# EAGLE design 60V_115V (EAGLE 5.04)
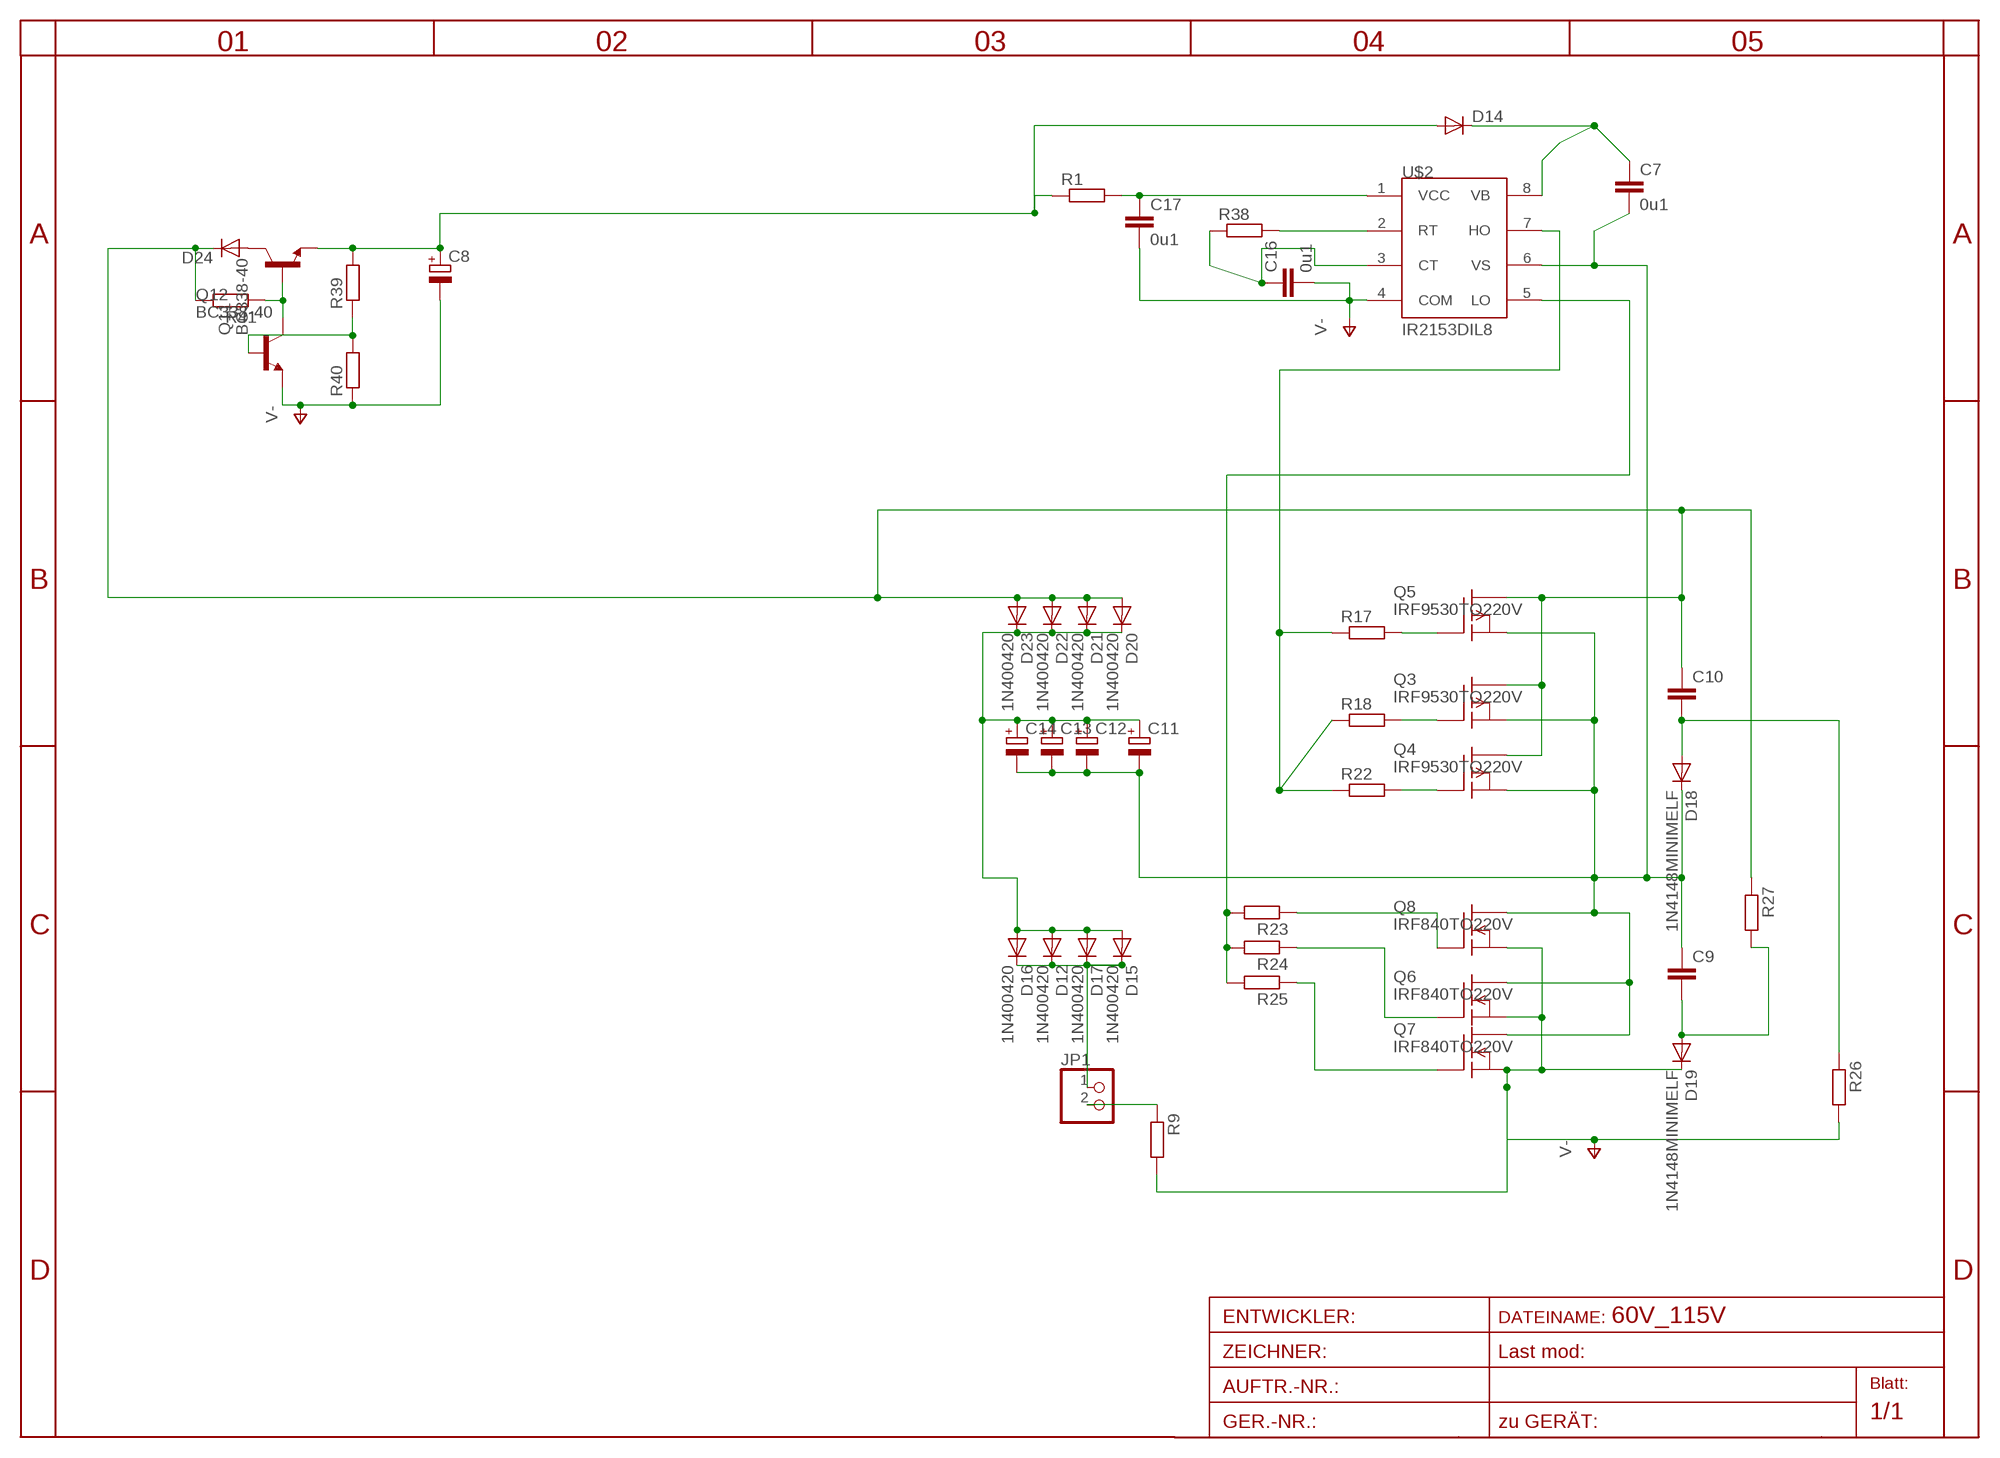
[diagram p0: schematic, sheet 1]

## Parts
C7  0u1  C-EU050-025X075  [C050-025X075]
C8  CPOL-EU5-13  [2,5-5-FLAT]
C9  C-EUC1812  [C1812]
C10  C-EUC1812K  [C1812K]
C11  CPOL-EUSANYO_SMD_E7  [SANYO-OSCON_SMD_E7]
C12  CPOL-EUSANYO_SMD_E7  [SANYO-OSCON_SMD_E7]
C13  CPOL-EUSANYO_SMD_E7  [SANYO-OSCON_SMD_E7]
C14  CPOL-EUSANYO_SMD_E7  [SANYO-OSCON_SMD_E7]
C16  0u1  C-EU025-050X050  [C025-050X050]
C17  0u1  C-EU050-030X075  [C050-030X075]
D12  1N400420  [DO41-20]
D14  DIODE-D-5  [D-5]
D15  1N400420  [DO41-20]
D16  1N400420  [DO41-20]
D17  1N400420  [DO41-20]
D18  1N4148MINIMELF  [MINIMELF]
D19  1N4148MINIMELF  [MINIMELF]
D20  1N400420  [DO41-20]
D21  1N400420  [DO41-20]
D22  1N400420  [DO41-20]
D23  1N400420  [DO41-20]
D24  DIODE-D-7.5  [D-7.5]
JP1  PINHD-1X2  [1X02]
Q3  IRF9530TO220V  [TO220V]
Q4  IRF9530TO220V  [TO220V]
Q5  IRF9530TO220V  [TO220V]
Q6  IRF840TO220V  [TO220V]
Q7  IRF840TO220V  [TO220V]
Q8  IRF840TO220V  [TO220V]
Q11  BC338-40  [TO92-EBC]
Q12  BC338-40  [TO92-EBC]
R1  R-EU_0204/2V  [0204V]
R9  R-EU_0207/10  [0207/10]
R17  R-EU_R1206  [R1206]
R18  R-EU_R1206  [R1206]
R22  R-EU_R1206  [R1206]
R23  R-EU_R1206  [R1206]
R24  R-EU_R1206  [R1206]
R25  R-EU_R1206  [R1206]
R26  R-EU_0207/25  [0207/25]
R27  R-EU_0207/30  [0207/30]
R38  R-EU_0204/2V  [0204V]
R39  R-EU_0207/10  [0207/10]
R40  R-EU_0204/2V  [0204V]
R41  R-EU_0207/10  [0207/10]
U$2  IR2153DIL8  [DIL08]

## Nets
CT: C16.1 R38.1 U$2.3(CT)
DRAIN: C7.2 C9.1 C11.- C12.- C13.- C14.- D18.C Q3.3(S) Q4.3(S) Q5.3(S) Q6.2(D) Q7.2(D) Q8.2(D) U$2.6(VS)
GATE: R17.1 R18.1 R22.1 U$2.7(HO)
N$1: JP1.2 R9.1
N$2: C11.+ C12.+ C13.+ C14.+ D12.A D15.A D16.A D17.A D20.C D21.C D22.C D23.C
N$4: Q3.1(G) R18.2
N$5: C8.+ D14.A Q11.E R1.1 R39.2
N$9: R23.2 R24.2 R25.2 U$2.5(LO)
N$11: Q5.1(G) R17.2
N$23: Q4.1(G) R22.2
N$24: C10.2 D18.A R26.1
N$25: Q7.1(G) R25.1
N$26: Q6.1(G) R24.1
N$27: Q8.1(G) R23.1
N$28: C9.2 D19.A R27.2
N$36: D24.A Q11.C
N$38: Q11.B Q12.C R41.1
N$40: R38.2 U$2.2(RT)
N$41: Q12.B R39.1 R40.2
OUT+: D12.C D15.C D16.C D17.C JP1.1
V-: C8.- C16.2 C17.2 D19.C Q6.3(S) Q7.3(S) Q8.3(S) Q12.E R9.2 R26.2 R40.1 U$2.4(COM)
VB: C7.1 D14.C U$2.8(VB)
VCC: C17.1 R1.2 U$2.1(VCC)
VIN: C10.1 D20.A D21.A D22.A D23.A D24.C Q3.2(D) Q4.2(D) Q5.2(D) R27.1 R41.2

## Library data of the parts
C7 C9 C10 C16 C17 = rcl-2:C-EU: CAPACITOR, European symbol
C8 C11-C14 = rcl-2:CPOL-EU: POLARIZED CAPACITOR, European symbol
D12 D15-D17 D20-D23 = diode-1:1N4004: DIODE
D14 D24 = diode-1:DIODE-: DIODE
D18 D19 = diode-1:1N4148: DIODE
JP1 = pinhead:PINHD-1X2: PIN HEADER
Q3-Q5 = transistor-fet:IRF9530: P-Channel Enhancement MOSFET (HEXFET); -100V; -12A; 0,3Ohm
Q6-Q8 = transistor-fet:IRF840: N-Channel Enhancement MOSFET (HEXFET); 500V; 8A; 0,85Ohm
Q11 Q12 = transistor-npn:BC338*: NPN Transistor
R1 R9 R17 R18 R22-R27 R38-R41 = rcl-2:R-EU_: RESISTOR, European symbol
U$2 = irf-2:IR2153

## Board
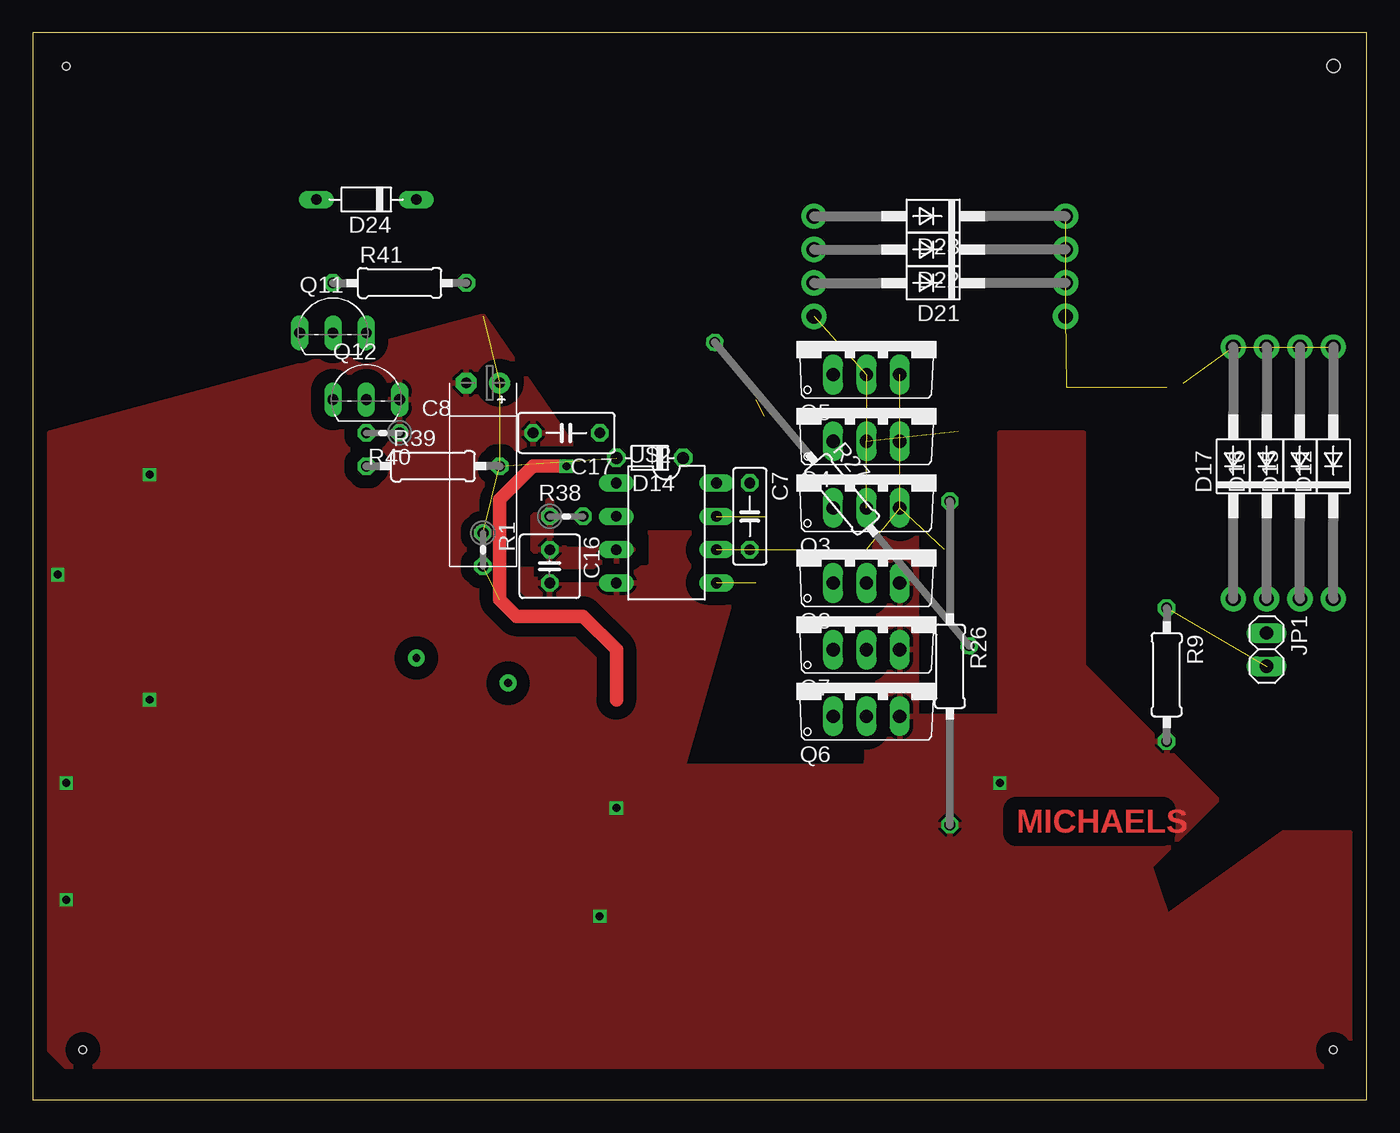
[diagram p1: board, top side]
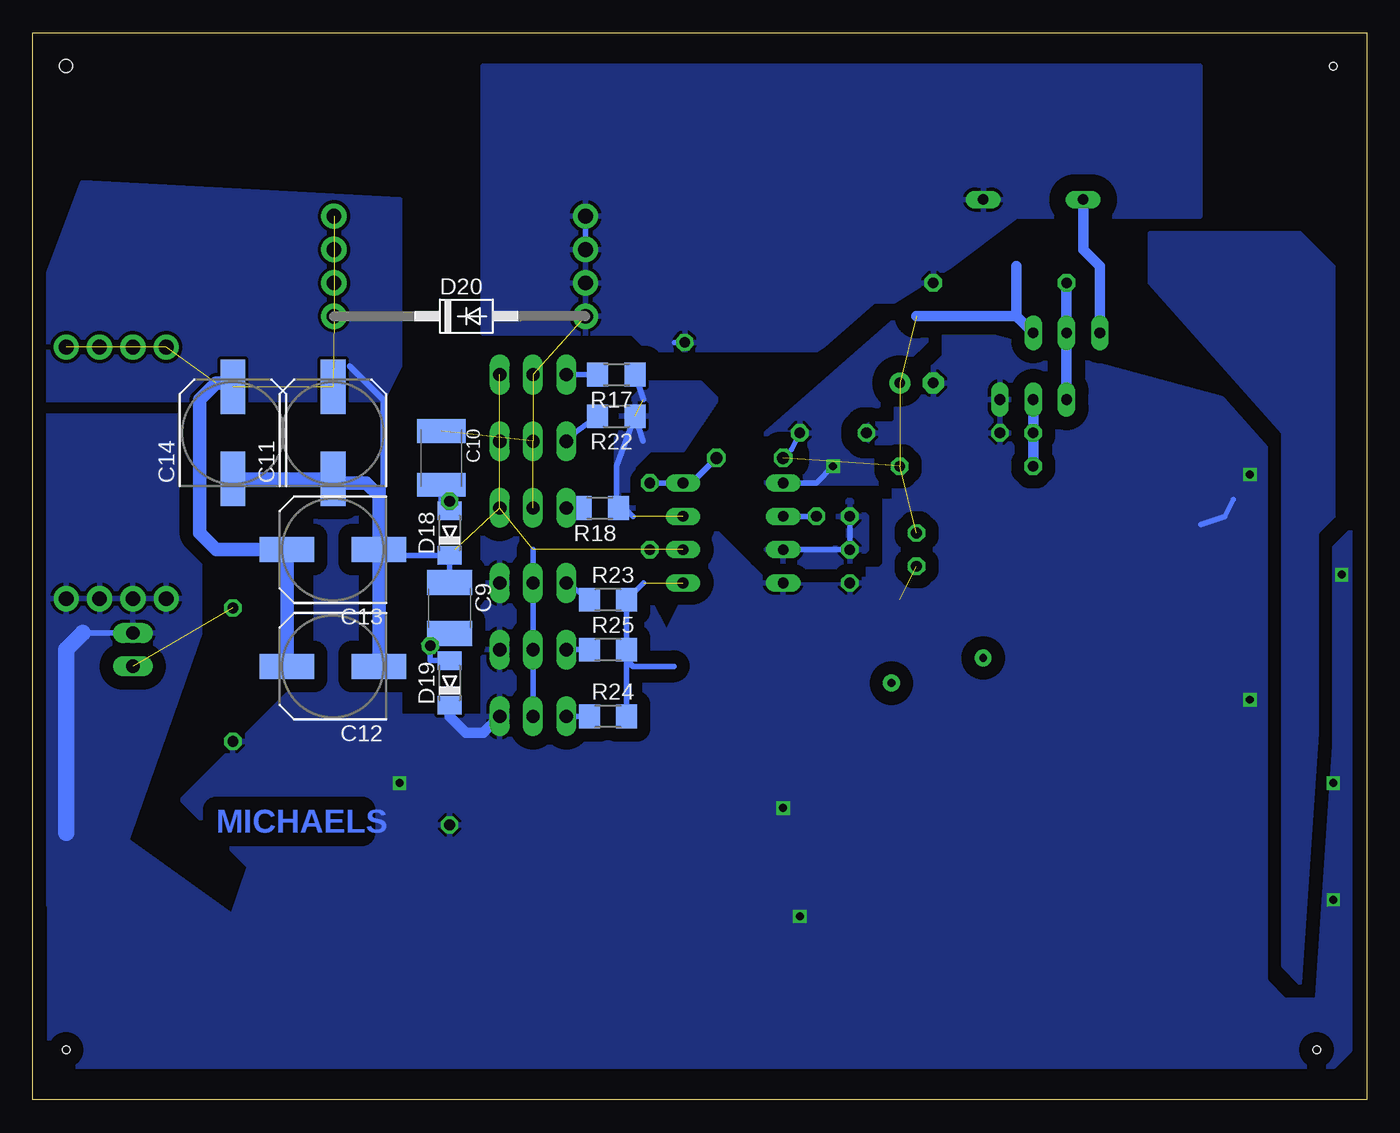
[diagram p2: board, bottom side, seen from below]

Size 101.6 x 81.28 mm. Coordinates in mm from the lower left corner, seen from the top.
Outline: 0,0 101.6,0 101.6,81.28 0,81.28 0,0
Copper layers (1*16): Top 0.035mm / dielectric 1.5mm / Bottom 0.035mm
Design rules "default": minimum track width 10mil, minimum drill 24mil, track to track 8mil, track to pad 8mil, pad to pad 8mil, via to via 8mil, smd to smd 8mil, copper to edge 40mil, drill to drill 8mil, minimum pad ring 10mil, minimum via ring 8mil, stop-mask expansion 4mil, vias tented up to drill 0mil, thermal gap 10mil
Holes 0.6 mm at 2.54,78.74 3.81,3.81 99.06,3.81
Holes 1 mm at 99.06,78.74

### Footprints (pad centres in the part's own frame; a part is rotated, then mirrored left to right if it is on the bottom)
C050-025X075 = drill 0.813 octagon: 1 -2.54,0; 2 2.54,0
2,5-5-FLAT = drill 0.813 pad 1.6 round: + -1.27,0 | drill 0.813 pad 1.6 octagon: - 1.27,0
C1812 = smd 1.9 x 3.4: 1 -1.95,0; 2 1.95,0
C1812K = smd 1.8 x 3.7: 1 -2.05,0; 2 2.05,0
SANYO-OSCON_SMD_E7 = smd 4.15 x 1.9: + 3.5,0; - -3.5,0
C025-050X050 = drill 0.813 octagon: 1 -1.27,0; 2 1.27,0
C050-030X075 = drill 0.813 octagon: 1 -2.54,0; 2 2.54,0
DO41-20 = drill 1.118 pad 1.93 round: A 9.08,0; C -10.08,0
D-5 = drill 0.9 octagon: A 2.54,0; C -2.54,0
MINIMELF = smd 1.4 x 1.8: A 1.7,0; C -1.7,0
D-7.5 = drill 0.813 long: A 3.81,0; C -3.81,0
1X02 = drill 1.016 long: 1 -1.27,0; 2 1.27,0
TO220V = drill 1.016 long: 1 -2.54,-2.54; 2 0,-2.54; 3 2.54,-2.54
TO92-EBC = drill 0.813 long: B 0,-1.27; C -2.54,-1.27; E 2.54,-1.27
0204V = drill 0.813 octagon: 1 -1.27,0; 2 1.27,0
0207/10 = drill 0.813 octagon: 1 -5.08,0; 2 5.08,0
R1206 = smd 1.6 x 1.803: 1 -1.422,0; 2 1.422,0
0207/25 = drill 0.813 octagon: 1 -12.58,0; 2 12.08,0
0207/30 = drill 0.813 octagon: 1 -15.08,0; 2 15.08,0
DIL08 = drill 0.813 long: 1 -3.81,-3.81; 2 -1.27,-3.81; 3 1.27,-3.81; 4 3.81,-3.81; 5 3.81,3.81; 6 1.27,3.81; 7 -1.27,3.81; 8 -3.81,3.81

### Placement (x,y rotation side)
C7  54.61,44.45 270 top
C8  34.29,54.61 180 top
C9  69.85,37.47 270 bottom
C10  70.48,48.9 270 bottom
C11  78.74,50.8 90 bottom
C12  78.74,33.02 180 bottom
C13  78.74,41.91 180 bottom
C14  86.36,50.8 90 bottom
C16  39.37,40.64 270 top
C17  40.64,50.8 180 top
D12  99.06,48.26 90 top
D14  46.99,48.9 180 top
D15  96.52,48.26 90 top
D16  93.98,48.26 90 top
D17  91.44,48.26 90 top
D18  69.85,43.18 90 bottom
D19  69.85,31.75 90 bottom
D20  68.58,59.69 0 bottom
D21  68.58,62.23 180 top
D22  68.58,64.77 180 top
D23  68.58,67.31 180 top
D24  25.4,68.58 180 top
JP1  93.98,34.29 270 top
Q3  63.5,47.62 0 top
Q4  63.5,52.7 0 top
Q5  63.5,57.78 0 top
Q6  63.5,31.75 0 top
Q7  63.5,36.83 0 top
Q8  63.5,41.91 0 top
Q11  22.86,59.69 0 top
Q12  25.4,54.61 0 top
R1  34.29,41.91 270 top
R9  86.36,32.38 270 top
R17  57.15,55.24 180 bottom
R18  58.42,45.09 180 bottom
R22  57.15,52.07 180 bottom
R23  57.78,38.1 0 bottom
R24  57.78,29.21 0 bottom
R25  57.78,34.29 0 bottom
R26  69.85,33.02 270 top
R27  61.63,46.14 310 top
R38  40.64,44.45 0 top
R39  30.48,48.26 0 top
R40  26.67,50.8 180 top
R41  27.94,62.23 0 top
U$2  48.26,43.18 270 top

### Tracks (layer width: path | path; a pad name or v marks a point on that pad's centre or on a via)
CT
  Bottom 0.406: R38.1 C16.1 U$2.3
  pour Bottom (isolate 0.813, rank 3): 45.72,41.91 40.64,41.91 39.37,43.18 40.64,44.45 39.37,45.72 38.1,44.45 38.1,41.91 39.37,40.64 44.45,40.64
  pour Top (isolate 0.813, rank 3): 45.72,41.91 40.64,41.91 39.37,43.18 40.64,44.45 39.37,45.72 38.1,44.45 38.1,41.91 39.37,40.64 44.45,40.64
DRAIN  (6 unrouted)
  Bottom 0.406: D18.C C9.1 | D18.C 69.42,41.91 | D18.C 74.5,41.48 74.93,41.91 C13.- | 77.47,55.88 74.93,53.34 74.93,43.49 75.24,43.18 | Q6.2 Q7.2 Q8.2 63.5,41.91
  Bottom 1.016: C12.- C13.- 75.24,43.18 75.24,46.03 76.2,46.99 78.43,46.99 C11.- 86.05,47.3 86.36,46.99 C14.-
  pour Bottom (isolate 0.254, rank 5): 101.6,53.34 74.93,53.34 73.66,55.88 73.66,68.58 97.79,69.85 101.6,59.69
GATE  (2 unrouted)
  Bottom 0.406: R18.1 57.15,45.09 57.15,45.72 | 57.15,45.72 57.15,48.26 R22.1 55.11,50.18 | R17.1 55.09,53.34 | 57.15,45.72 55.88,44.45
  pour Bottom (isolate 0.813, rank 2): 49.53,53.34 50.8,54.61 53.34,54.61 54.61,54.61 57.15,52.07 57.15,44.45 55.88,44.45 55.88,48.26 54.61,49.53 52.07,49.53
N$1  (1 unrouted)
N$2  (9 unrouted)
  Bottom 1.016: C12.+ C13.+ 87.63,41.91 88.9,43.18 88.9,53.34 87.63,54.61 86.67,54.61 C14.+
N$4
  Bottom 0.406: R18.2 Q3.1
N$5  (4 unrouted)
  Bottom 0.813: Q11.E 26.67,59.69 | 26.67,59.69 26.67,63.5 | 26.67,59.69 34.29,59.69
N$8  (via drill 0.6 pad 1.27)
  other vias: 36.2,31.75
N$9  (1 unrouted)
  Bottom 0.406: 55.09,39.37 R23.2 R25.2 56.36,33.5 | 56.36,33.5 55.88,33.02 52.77,33.02 | R24.2 56.36,33.5
N$11
  Bottom 0.406: R17.2 Q5.1
N$23
  Bottom 0.406: R22.2 60.33,50.8 Q4.1
N$24
  Bottom 0.406: D18.A R26.1 70.48,45.6 C10.2
N$25
  Bottom 0.406: R25.1 Q7.1
N$26
  Bottom 0.406: R24.1 Q6.1
N$27
  Bottom 0.406: R23.1 Q8.1
N$28
  Bottom 0.406: C9.2 71.33,35.52 R27.2 71.33,33.45 D19.A
N$35  (via drill 0.6 pad 1.27)
  other vias: 29.21,33.66
N$36
  Bottom 0.813: D24.A 21.59,64.77 20.32,63.5 Q11.C
N$38
  Bottom 0.813: R41.1 Q11.B Q12.C
N$40
  Bottom 0.406: R38.2 U$2.2
N$41
  Bottom 0.813: Q12.B R40.2 R39.1
OUT+
  Bottom 0.406: 97.79,35.56 JP1.1
  Bottom 1.27: 97.79,35.56 99.06,34.29 99.06,20.32
  pour Bottom (isolate 1.016, rank 5): 88.9,52.07 101.6,52.07 101.6,15.24 96.52,13.97 88.9,35.56
V+
  pour Bottom (isolate 0.61, rank 3): 16.51,66.04 5.08,66.04 2.54,63.5 2.54,44.45 3.81,43.18 3.81,27.94 5.08,8.89 6.35,10.16 6.35,50.8 16.51,62.23
V-  (via drill 0.6)
  Bottom 0.406: 12.64,43.81 10.79,44.45 10.16,45.72
  Bottom 0.813: D19.C 69.85,29.21 68.58,27.94 67.31,27.94 Q6.3
  other vias: 44.45,22.23 43.18,13.97 73.66,24.13 8.89,30.48 8.89,47.62 1.91,40.01 2.54,24.13 2.54,15.24
  pour Top (isolate 1.016, rank 5): 1.27,50.8 34.29,59.69 45.72,43.18 54.61,43.18 49.53,25.4 63.5,25.4 64.77,57.15 67.31,57.15 67.31,29.21 73.66,29.21 73.66,50.8 80.01,50.8 80.01,33.02 90.17,22.86 85.09,17.78 86.36,13.97 95.25,20.32 100.33,20.32 100.33,3.81 99.06,2.54 2.54,2.54 1.27,3.81
  pour Bottom (isolate 1.016, rank 5): 1.27,50.8 34.29,59.69 45.72,39.37 49.53,43.18 53.34,35.56 64.77,57.15 67.31,57.15 67.31,29.21 73.66,29.21 73.66,50.8 80.01,50.8 80.01,33.02 90.17,22.86 85.09,17.78 86.36,13.97 95.25,20.32 100.33,20.32 100.33,3.81 99.06,2.54 2.54,2.54 1.27,3.81
VB
  Bottom 0.406: C7.1 U$2.8 51.44,46.99 D14.C
VCC  (via drill 0.6)  (1 unrouted)
  Top 1.016: v40.64,48.26 38.1,48.26 35.56,45.72 35.56,38.1 36.83,36.83 41.91,36.83 44.45,34.29 44.45,30.48
  Bottom 0.406: 43.81,49.53 C17.1 | U$2.1 41.91,46.99 v40.64,48.26
  pour Bottom (isolate 1.27, rank 2): 24.13,67.31 26.67,67.31 26.67,66.04 30.48,62.23 35.56,59.69 45.72,50.8 45.72,46.99 33.02,46.99 40.64,50.8 39.37,50.8 35.56,54.61 35.56,55.88 33.02,58.42 25.4,58.42 25.4,59.69 24.13,60.96
VIN  (4 unrouted)
  Bottom 0.406: D22.A D23.A | R27.1 52.7,57.69
  pour Bottom (isolate 1.27, rank 3): 12.7,78.74 67.31,78.74 67.31,58.42 55.88,58.42 54.61,57.15 41.91,57.15 31.75,63.5 26.67,67.31 12.7,67.31

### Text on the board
Top: MICHAELS
Bottom: MICHAELS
